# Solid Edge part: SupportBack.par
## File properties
Author: wojci
Template: ISO Metric Part.par
Last saved by: wojci
Revision: 19
Application: Solid Edge
Username: wojci
Accuracy: 0.990
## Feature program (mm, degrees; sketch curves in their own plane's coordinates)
sketch for "unnamed Protrusion 1" plane through (0, 0, 0) normal (1, 0, 0) x-axis (0, 1, 0)
  line (11.5, 31.375) -> (29.6338, 58.2787)
  line (11.5, 3.75) -> (11.5, 31.375)
  line (5, 0) -> (11.5, 3.75)
  line (0, 0) -> (5, 0)
  line (0, 0) -> (0, 1.75)
  line (2, 1.75) -> (0, 1.75)
  line (2, 3.75) -> (2, 1.75)
  line (0, 3.75) -> (2, 3.75)
  line (0, 3.75) -> (0, 67)
  line (0, 67) -> (5, 67)
  line (5, 67) -> (11.5, 62.75)
  line (11.5, 62.75) -> (17.4348, 68.497)
extrude "unnamed Protrusion 1" add finite 24 along +normal
fillet "Round_1" radius 10
fillet "Round_2" radius 40
sketch for "Hole_1" plane through (24, 14, 33.875) normal (1, 0, 0) x-axis (0, 0.558918, 0.829223)
  hole centre (28.9741, 8.6758) bore radius 1.6
hole "Hole_1" diameter 3.2 through
sketch for "ExtrudedProtrusion_2" #1 plane through (12, 0, 35.375) normal (0, -1, 0) x-axis (1, 0, 0)
  line (0.75, 22.125) -> (9.75, 22.125)
  line (9.75, 22.125) -> (9.75, 31.625)
  line (9.75, 31.625) -> (0.75, 31.625)
  line (0.75, 31.625) -> (0.75, 22.125)
  dimension (linear) = 9.75
  dimension (linear) = 9.75
  dimension (linear) = 9.75
  dimension (linear) = 9.75
  dimension (linear) = 9.75
sketch for "ExtrudedProtrusion_2" #2 plane through (12, 0, 35.375) normal (0, -1, 0) x-axis (1, 0, 0)
  line (0.75, -31.375) -> (9.75, -31.375)
  line (9.75, -31.375) -> (9.75, -21.125)
  line (9.75, -21.125) -> (0.75, -21.125)
  line (0.75, -21.125) -> (0.75, -31.375)
sketch for "ExtrudedProtrusion_2" #3 plane through (12, 0, 35.375) normal (0, -1, 0) x-axis (1, 0, 0)
  line (0.75, -33.875) -> (9.75, -33.875)
  line (9.75, -33.875) -> (9.75, -35.375)
  line (9.75, -35.375) -> (0.75, -35.375)
  line (0.75, -35.375) -> (0.75, -33.875)
extrude "ExtrudedProtrusion_2" add finite 1.25 along +normal
sketch for "unnamed Cutout 1" plane through (12, 1.875, 67) normal (0, 0, 1) x-axis (1, 0, 0)
  line (2, 5.125) -> (0, 13.125)
  line (0, 13.125) -> (0, 29.125)
  line (12, 29.125) -> (0, 29.125)
  line (12, 29.125) -> (12, 3.125)
  line (2, 5.125) -> (12, 3.125)
extrude "unnamed Cutout 1" cut through along +normal
sketch for "Hole_2" plane through (17.25, -1.25, 62.25) normal (0, -1, 0) x-axis (1, 0, 0)
  hole centre (0, -55.75) bore radius 1.2295
hole "Hole_2" nominal diameter 3 through  ThreadDepth = 2 mm
sketch for "unnamed Hole 1" plane through (17.25, -1.25, 62.25) normal (0, -1, 0) x-axis (1, 0, 0)
  hole centre (0, 0.75) bore radius 1.2295
hole "unnamed Hole 1" through
sketch for "Hole_6" plane through (17.25, 3.25, 62.25) normal (0, -1, 0) x-axis (1, 0, 0)
hole "Hole_6" diameter 6.5 through
sketch for "unnamed Hole 2" plane through (17.25, 3.25, 62.25) normal (0, -1, 0) x-axis (1, 0, 0)
hole "unnamed Hole 2" through
sketch for "unnamed Cutout 2" plane through (17.25, 3.25, 63) normal (0, 1, 0) x-axis (-1, 0, 0)
extrude "unnamed Cutout 2" cut through along +normal
sketch for "ExtrudedProtrusion_3" plane through (12, 1.875, 67) normal (0, 0, 1) x-axis (-1, 0, 0)
  line (-12, 1.875) -> (-12, -3.125)
  line (-12, -3.125) -> (-8.5, -3.125)
  line (-8.5, -3.125) -> (-8.5, -1.375)
  line (-8.5, -1.375) -> (-1.9992, -1.375)
  line (-1.9992, -1.375) -> (-1.9992, -3.125)
  line (-1.9992, -3.125) -> (12, -3.125)
  line (12, -3.125) -> (12, 1.875)
  line (12, 1.875) -> (-0.75, 1.875)
  line (-0.75, 1.875) -> (-0.75, 3.125)
  line (-0.75, 3.125) -> (-9.75, 3.125)
  line (-9.75, 3.125) -> (-9.75, 1.875)
  line (-9.75, 1.875) -> (-12, 1.875)
extrude "ExtrudedProtrusion_3" add finite 0.5 along +normal
sketch for "ExtrudedProtrusion_4" plane through (12, 1.875, 67.5) normal (0, 0, 1) x-axis (-1, 0, 0)
  line (-12, 1.875) -> (-12, -3.125)
  line (-12, -3.125) -> (-8.5, -3.125)
  line (-8.5, -3.125) -> (-8.5, -1.375)
  line (-8.5, -1.375) -> (-1.9992, -1.375)
  line (-1.9992, -1.375) -> (-1.9992, -3.125)
  line (-1.9992, -3.125) -> (1.5008, -3.125)
  line (1.5008, -3.125) -> (1.5008, 1.875)
  line (1.5008, 6.875) -> (1.5008, 1.875)
  line (-12, 6.875) -> (1.5008, 6.875)
  line (-12, 1.875) -> (-12, 6.875)
  dimension (linear) = 1.9992
  dimension (linear) = 12
extrude "ExtrudedProtrusion_4" add finite 5 along +normal
fillet "Round_4" radius 3.25
chamfer "Chamfer_2" setback 3
fillet "Round_5" radius 5
chamfer "Chamfer_3" setback 3
chamfer "Chamfer_4" setback 5
fillet "Round_6" radius 13
fillet "Round_7" radius 3.5
logasc func "Lip_Groove_1"  LipOrGrooveWidth = 1.25 mm; LipOrGrooveHeight = 0.4 mm
logasc func "Lip_Groove_2"  LipOrGrooveWidth = 1.25 mm; LipOrGrooveHeight = 0.4 mm
logasc func "Lip_Groove_3"  LipOrGrooveWidth = 1.25 mm; LipOrGrooveHeight = 0.4 mm
logasc func "Lip_Groove_4"  LipOrGrooveWidth = 1.25 mm; LipOrGrooveHeight = 0.4 mm
pattern "unnamed Pattern 1" of "Hole_2", "unnamed Hole 1"
pattern "unnamed Pattern 2" of "Hole_6", "unnamed Hole 2"
Other named dimensions: "Hole_4": Plane_Distance = 4.5 mm
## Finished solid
Body 1: solid body, 55 faces, 145 edges, 90 vertices.
  Faces by surface: plane 41, cylinder 13, spline 1
  Edges by curve: line 103, circle 23, ellipse 7, curve on surface 6, intersection 6
Bounding box of the edges (mm; curved faces can reach further): 24.000 x 36.000 x 72.500, from (0, -5, 0) to (24, 31, 72.5).
Cylindrical faces by radius (mm): R1.2295 x4, R1.6 x1, R3.25 x3, R3.5 x1, R8 x1, R10 x1, R13 x1, R40 x1
Planar faces by outward normal: +x 7, +y 4, +z 5, -x 6, -y 7, -z 5, oblique 7
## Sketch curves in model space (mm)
line (12, 27.9, 67) -> (12, 28, 67)
line (12, 0, 67) -> (12, 31, 67)
line (14, 31, 67) -> (14, -1.25, 67)
line (17.25, -1.25, 67) -> (17.25, 31, 67)
line (0, 15, 67) -> (24, 15, 67)
line (14, 7, 67) -> (24, 5, 67)
line (14, 7, 67) -> (12, 15, 67)
line (12, 15, 67) -> (12, 31, 67)
line (24, 31, 67) -> (12, 31, 67)
line (24, 31, 67) -> (24, 5, 67)
line (0, 7, 67) -> (24, 7, 67)
line (0, 0, 62.75) -> (0, 23, 62.75)
line (0, 0, 67) -> (0, 5, 67)
line (0, 5, 67) -> (0, 11.5, 62.75)
line (0, 11.5, 62.75) -> (0, 17.4348, 68.497)
arc centre (0, 23, 62.75) radius 8 from (0, 17.4348, 68.497) through (0, 28.4947, 68.5644) to (0, 29.6338, 58.2787)
line (0, 11.5, 31.375) -> (0, 29.6338, 58.2787)
line (0, 11.5, 3.75) -> (0, 11.5, 31.375)
line (0, 5, 0) -> (0, 11.5, 3.75)
line (0, 0, 0) -> (0, 5, 0)
line (0, 0, 0) -> (0, 0, 1.75)
line (0, 2, 1.75) -> (0, 0, 1.75)
line (0, 2, 3.75) -> (0, 2, 1.75)
line (0, 0, 3.75) -> (0, 2, 3.75)
line (0, 0, 3.75) -> (0, 0, 67)
line (0, 11.5, 62.75) -> (0, 11.5, 0)
line (0, 5, 67) -> (0, 5, 0)
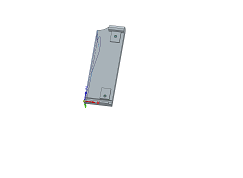
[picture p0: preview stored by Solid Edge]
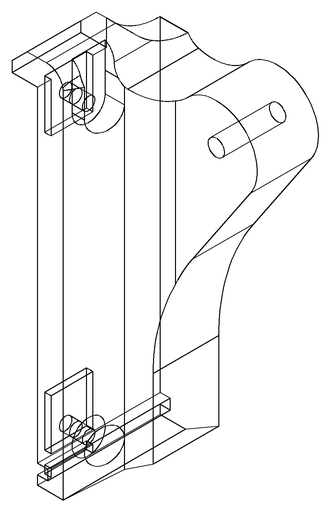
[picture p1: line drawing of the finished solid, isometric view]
